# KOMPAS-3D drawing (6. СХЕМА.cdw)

Referenced files in C:\KOMPAS-3D V12\Sys\: Graphic.lcs
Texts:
  ДП.11.213.05.000.00.Э3
  Телятник на 120 голов в СПК колхоз "Дзержинского" Даниловского МР Ярославской обл. Схема электрическая принципиальная
  HL1
  HL2
  HL3
  SA1
  SA2
  VD1
  VS1
  VS2
  VD2
  KV1
  VS3
  VS4
  VD4
  KV2
  VD3
  VS5
  VS6
  VD6
  KV3
  VD5
  SB1
  HL4
  HL5
  KT1
  HL6
  KT2
  SA3
  Сеть
  Токовая
  защита
  Авария
  Программа
  Ступень
  Контроль
  температуры
  Задатчик
  Поз.
  обозн.
  Кол.
  ТБ1
  ЕК1...ЕК3
  По месту:
  Нагревательные секции электрообогре-
  ваемого пола
  из провода ПОСХВ
  ТБ-1
  Тиристорный регулируемый блок ТБР-10
  Регулятор темперапуры ПТР-2Б/0,4
  комплект
  Шкаф управления:
  Автоматический выключатель ВА51-31
  Токовое реле РТ-067ЭТ, 50Гц; 220В; 8А.
  Реле времени ТЭ-15
  Промежуточное реле РЭК77/3, 220В; 10А.
  Трансформатор тока ТТИ-А-5, 0,66кВ; 5А.
  Дверь шкафа:
  HL1, HL2, HL3
  HL4,HL6
  Переключатель УП5312-С29У3
  Лампа АL-22, неон/230В, цилиндр
  Датчик температуры
  Звонок БПР - 1А
  IНА =100А; IТР =20А; IОТС =10 IНОМ.
  Переключатель УП5312-C29У3
  Переключатель УП5311-И25У3
  Вольтметр
  цвет зелёный, D=22 мм
  цвет красный, D=22 мм
  Кнопка SB-7 "Стоп" 1з+1р
  SВ1
  цвет красный, D=28 мм
  в комплекте с ПТР-2Б/0,4
  Избиратель управления
  УП5312-С29У3
  № кон-
  такта
  № сек-
  ции
  III
  откл.
  вкл.
  Шина, общее изображение ГОСТ 21.614-88
  Стили документа
  Куракин.
  ФГОУ ВПО ЯГСХА
  Шмигель
  ДП08Ф040200009Э0-
  Орлов
  Телятник на 120 голов
  в СПК колхоз "Дзержинского"
  Даниловского МР Ярославской обл.
  Схема электрическая принципиальная
  Схема управления системой
  обогрева пола
Dimensions and other numbers on the sheet: 0,5Рном; 0,25Рном; 3; 1; 5; 4; 2; 6; 7; 8; 9; 10; 0; +45; -45; 1 - 2; 3 - 4; 5 - 6; 7 - 8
